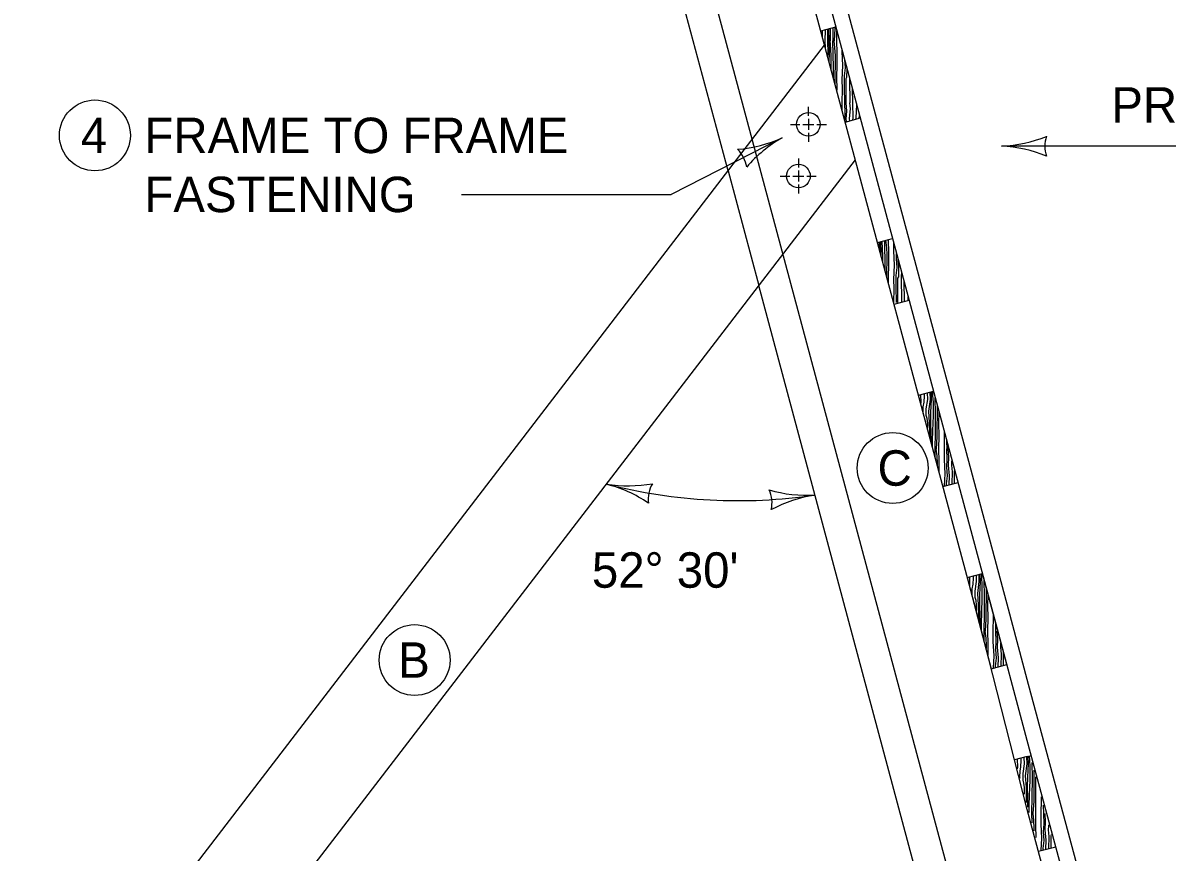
# Model space of a CAD drawing. Extents: x 49991 to 79985, y 47703 to 60542.
# Drawn here: x 50011.049 to 50012.986, y 49994.102 to 49995.507 of the extents above; entities that cross this region are included whole.
import ezdxf

# ---------------------------------------------------------------- set-up
doc = ezdxf.new("R2010")
doc.units = 0
for name, color, linetype in [('Level 1', 7, 'Continuous'), ('Level 2', 7, 'Continuous'), ('Level 3', 7, 'Continuous'), ('Level 33', 7, 'Continuous'), ('Level 4', 7, 'Continuous'), ('Level 5', 7, 'Continuous')]:
    doc.layers.add(name, color=color, linetype=linetype)

msp = doc.modelspace()

# ---------------------------------------------------------------- linework, layer by layer
at = {"layer": 'Level 1'}
for p, q in [((50012.7492, 49993.5717), (50012.0592, 49996.1469)), ((50012.6896, 49994.5138), (50012.2531, 49996.1429)), ((50012.7172, 49994.5138), (50012.2788, 49996.1497)), ((50012.2427, 49995.2562), (50012.0075, 49996.134)), ((50012.6693, 49994.4868), (50012.2343, 49996.1103)), ((50012.3996, 49995.4932), (50012.4253, 49995.5001)), ((50011.049, 49993.7005), (50012.4061, 49995.4691)), ((50012.441, 49995.3389), (50012.4667, 49995.3458)), ((50011.2503, 49993.7005), (50012.4582, 49995.2747)), ((50012.4956, 49995.135), (50012.5213, 49995.1419)), ((50012.655, 49993.7175), (50012.2948, 49995.0618)), ((50012.5237, 49995.0303), (50012.5493, 49995.0372)), ((50012.565, 49994.876), (50012.5907, 49994.8829)), ((50012.6063, 49994.7218), (50012.632, 49994.7286)), ((50012.6477, 49994.5675), (50012.6734, 49994.5744)), ((50012.9351, 49993.7005), (50012.7492, 49994.3944)), ((50012.9075, 49993.7005), (50012.7492, 49994.2915)), ((50012.7492, 49994.264), (50012.7561, 49994.2658)), ((50012.8544, 49993.782), (50012.7492, 49994.1747)), ((50012.7682, 49994.1037), (50012.7974, 49994.1115))]:
    msp.add_line(p, q, dxfattribs=at)
for points in [[(50012.4071, 49995.4763), (50012.4074, 49995.4953)], [(50012.4116, 49995.4763), (50012.4114, 49995.4963)], [(50012.4137, 49995.4763), (50012.4135, 49995.4969)], [(50012.4159, 49995.4763), (50012.416, 49995.4893), (50012.4162, 49995.4976)], [(50012.4204, 49995.4763), (50012.4208, 49995.4989)], [(50012.4227, 49995.4763), (50012.4239, 49995.4976), (50012.4239, 49995.4997)], [(50012.4025, 49995.4823), (50012.4025, 49995.4939)], [(50012.4074, 49995.464), (50012.407, 49995.4768)], [(50012.4114, 49995.4492), (50012.4123, 49995.4556), (50012.4115, 49995.4763)], [(50012.4136, 49995.4409), (50012.4144, 49995.4556), (50012.4136, 49995.4773)], [(50012.4173, 49995.4272), (50012.4173, 49995.4275), (50012.4173, 49995.4503), (50012.4166, 49995.4621), (50012.4157, 49995.4769)], [(50012.421, 49995.4133), (50012.4212, 49995.4308), (50012.4203, 49995.4767)], [(50012.424, 49995.4023), (50012.4243, 49995.4518), (50012.4237, 49995.4646), (50012.4224, 49995.4766)], [(50012.427, 49995.3909), (50012.4271, 49995.3944), (50012.4268, 49995.4145), (50012.4273, 49995.4351), (50012.4271, 49995.4556), (50012.4267, 49995.4768)], [(50012.4268, 49995.4763), (50012.427, 49995.4936)], [(50012.427, 49995.4936), (50012.427, 49995.4936)], [(50012.4359, 49995.3714), (50012.4365, 49995.3949), (50012.4359, 49995.4102), (50012.4371, 49995.4345), (50012.4359, 49995.4586), (50012.4359, 49995.4603)], [(50012.4136, 49995.4409), (50012.4136, 49995.4409)], [(50012.4405, 49995.3714), (50012.4399, 49995.3982), (50012.4396, 49995.4172), (50012.4413, 49995.4308), (50012.4402, 49995.4444)], [(50012.4173, 49995.4272), (50012.4173, 49995.4272)], [(50012.4427, 49995.3714), (50012.4424, 49995.408), (50012.4428, 49995.4125), (50012.444, 49995.4147), (50012.4444, 49995.4287)], [(50012.4444, 49995.4287), (50012.4444, 49995.4288)], [(50012.4494, 49995.3714), (50012.449, 49995.4114)], [(50012.4538, 49995.3714), (50012.4533, 49995.3953)], [(50012.4359, 49995.3577), (50012.4359, 49995.3717)], [(50012.4402, 49995.3418), (50012.4408, 49995.3542), (50012.4404, 49995.3715)], [(50012.4433, 49995.3395), (50012.4428, 49995.3442), (50012.4435, 49995.3575), (50012.4425, 49995.3715)], [(50012.4488, 49995.341), (50012.4485, 49995.3442), (50012.4487, 49995.3505), (50012.4501, 49995.3612), (50012.4491, 49995.3715)], [(50012.454, 49995.3424), (50012.4542, 49995.3452), (50012.4537, 49995.3717)], [(50012.459, 49995.3437), (50012.4594, 49995.346), (50012.4601, 49995.3565), (50012.4604, 49995.3687)], [(50012.4402, 49995.3418), (50012.4402, 49995.3418)], [(50012.4647, 49995.3453), (50012.4654, 49995.3501)], [(50012.4997, 49995.1197), (50012.4991, 49995.1359)], [(50012.5016, 49995.1124), (50012.5019, 49995.1175), (50012.5012, 49995.1365)], [(50012.5048, 49995.1005), (50012.5048, 49995.1122), (50012.5041, 49995.124), (50012.5033, 49995.1371)], [(50012.5086, 49995.0863), (50012.5087, 49995.0926), (50012.5078, 49995.1383)], [(50012.5115, 49995.0754), (50012.5118, 49995.1137), (50012.5112, 49995.1265), (50012.5098, 49995.1388)], [(50012.5145, 49995.0644), (50012.5143, 49995.0764), (50012.5148, 49995.0969), (50012.5146, 49995.1175), (50012.5142, 49995.14)], [(50012.5234, 49995.0333), (50012.524, 49995.0568), (50012.5234, 49995.0721), (50012.5246, 49995.0964), (50012.5234, 49995.1205), (50012.5234, 49995.1341)], [(50012.528, 49995.0333), (50012.5274, 49995.0601), (50012.5271, 49995.0791), (50012.5288, 49995.0926), (50012.5276, 49995.1072), (50012.528, 49995.1163)], [(50012.5302, 49995.0333), (50012.5299, 49995.0699), (50012.5303, 49995.0744), (50012.5315, 49995.0766), (50012.5319, 49995.0929), (50012.5308, 49995.1062)], [(50012.5369, 49995.0339), (50012.5365, 49995.0786), (50012.5366, 49995.0842)], [(50012.5413, 49995.0351), (50012.5406, 49995.0695)], [(50012.5478, 49995.0368), (50012.5478, 49995.0426)], [(50012.5478, 49995.0426), (50012.5478, 49995.0426)], [(50012.569, 49994.8607), (50012.5693, 49994.8637), (50012.569, 49994.8771)], [(50012.5732, 49994.8452), (50012.5729, 49994.8472), (50012.5731, 49994.8567), (50012.5745, 49994.8645), (50012.5752, 49994.875), (50012.5753, 49994.8788)], [(50012.5805, 49994.8181), (50012.5806, 49994.8291), (50012.5795, 49994.8368), (50012.5782, 49994.8419), (50012.5782, 49994.8529), (50012.5806, 49994.8692), (50012.5802, 49994.8801)], [(50012.5843, 49994.8039), (50012.5842, 49994.8101), (50012.5838, 49994.8299), (50012.5825, 49994.8492), (50012.5851, 49994.8692), (50012.5847, 49994.8813)], [(50012.5865, 49994.7957), (50012.5863, 49994.8101), (50012.5859, 49994.8299), (50012.5861, 49994.8469), (50012.5873, 49994.8692), (50012.5868, 49994.8819)], [(50012.5888, 49994.7871), (50012.5888, 49994.7981), (50012.5893, 49994.8166), (50012.5902, 49994.8412), (50012.5902, 49994.864), (50012.5895, 49994.8757), (50012.5891, 49994.8825)], [(50012.5933, 49994.785), (50012.5938, 49994.8133), (50012.594, 49994.8444), (50012.5935, 49994.8718)], [(50012.5935, 49994.8718), (50012.5935, 49994.8719)], [(50012.5955, 49994.785), (50012.5968, 49994.8063), (50012.5972, 49994.8584)], [(50012.5997, 49994.785), (50012.5999, 49994.8081), (50012.5997, 49994.8281), (50012.6001, 49994.8473)], [(50012.6088, 49994.785), (50012.6093, 49994.8086), (50012.6092, 49994.8136)], [(50012.613, 49994.7991), (50012.613, 49994.7992)], [(50012.6133, 49994.785), (50012.613, 49994.7991)], [(50012.5935, 49994.7695), (50012.5933, 49994.7855)], [(50012.5972, 49994.7558), (50012.5972, 49994.7606), (50012.5965, 49994.7734), (50012.5952, 49994.785)], [(50012.6002, 49994.7446), (50012.5999, 49994.7644), (50012.5997, 49994.7846)], [(50012.609, 49994.7225), (50012.61, 49994.7433), (50012.6088, 49994.7674), (50012.6088, 49994.7854)], [(50012.6125, 49994.7234), (50012.6125, 49994.726), (50012.6142, 49994.7395), (50012.613, 49994.7541), (50012.6137, 49994.7679), (50012.6132, 49994.7852)], [(50012.6169, 49994.7246), (50012.6173, 49994.7398), (50012.6157, 49994.7578), (50012.6164, 49994.7711), (50012.6154, 49994.7854)], [(50012.6156, 49994.785), (50012.6155, 49994.7897)], [(50012.6219, 49994.726), (50012.6225, 49994.7463), (50012.6214, 49994.7578), (50012.6216, 49994.7641), (50012.6219, 49994.7662)], [(50012.5972, 49994.7557), (50012.5972, 49994.7558)], [(50012.626, 49994.727), (50012.6261, 49994.7476), (50012.6263, 49994.7496)], [(50012.6519, 49994.5521), (50012.6522, 49994.5551), (50012.6519, 49994.5685)], [(50012.6561, 49994.5366), (50012.6558, 49994.5386), (50012.656, 49994.5481), (50012.6574, 49994.5559), (50012.6581, 49994.5664), (50012.6582, 49994.5702)], [(50012.6634, 49994.5095), (50012.6635, 49994.5205), (50012.6624, 49994.5282), (50012.6611, 49994.5333), (50012.6611, 49994.5443), (50012.6635, 49994.5606), (50012.6631, 49994.5715)], [(50012.6672, 49994.4953), (50012.6671, 49994.5015), (50012.6667, 49994.5213), (50012.6654, 49994.5406), (50012.668, 49994.5606), (50012.6676, 49994.5727)], [(50012.6694, 49994.4871), (50012.6692, 49994.5015), (50012.6688, 49994.5213), (50012.669, 49994.5383), (50012.6702, 49994.5606), (50012.6697, 49994.5733)], [(50012.6717, 49994.4785), (50012.6717, 49994.4895), (50012.6722, 49994.508), (50012.6731, 49994.5326), (50012.6731, 49994.5554), (50012.6724, 49994.5671), (50012.672, 49994.5739)], [(50012.6762, 49994.4764), (50012.6767, 49994.5047), (50012.6769, 49994.5358), (50012.6764, 49994.5632)], [(50012.6784, 49994.4764), (50012.6797, 49994.4977), (50012.6801, 49994.5498)], [(50012.6826, 49994.4764), (50012.6828, 49994.4995), (50012.6826, 49994.5195), (50012.683, 49994.5387)], [(50012.6832, 49994.5368), (50012.6832, 49994.5368)], [(50012.6917, 49994.4764), (50012.6922, 49994.5), (50012.6921, 49994.505)], [(50012.6962, 49994.4764), (50012.6959, 49994.4905)], [(50012.6764, 49994.4609), (50012.6762, 49994.4769)], [(50012.6801, 49994.4472), (50012.6801, 49994.452), (50012.6794, 49994.4648), (50012.6781, 49994.4764)], [(50012.6831, 49994.436), (50012.6828, 49994.4558), (50012.6826, 49994.4761)], [(50012.6919, 49994.4139), (50012.6929, 49994.4347), (50012.6917, 49994.4588), (50012.6917, 49994.4768)], [(50012.6954, 49994.4148), (50012.6954, 49994.4174), (50012.6971, 49994.4309), (50012.6959, 49994.4455), (50012.6966, 49994.4593), (50012.6962, 49994.4766)], [(50012.6998, 49994.416), (50012.7002, 49994.4312), (50012.6986, 49994.4492), (50012.6993, 49994.4625), (50012.6983, 49994.4768)], [(50012.7048, 49994.4174), (50012.7054, 49994.4377), (50012.7043, 49994.4492), (50012.7045, 49994.4555), (50012.7048, 49994.4576)], [(50012.7089, 49994.4184), (50012.709, 49994.439), (50012.7092, 49994.441)], [(50012.7328, 49994.2432), (50012.7331, 49994.2462), (50012.7328, 49994.2596)], [(50012.737, 49994.2277), (50012.7367, 49994.2297), (50012.7369, 49994.2392), (50012.7383, 49994.247), (50012.739, 49994.2575), (50012.7391, 49994.2613)], [(50012.7443, 49994.2006), (50012.7444, 49994.2116), (50012.7433, 49994.2193), (50012.742, 49994.2244), (50012.742, 49994.2354), (50012.7444, 49994.2517), (50012.744, 49994.2626)], [(50012.7481, 49994.1864), (50012.748, 49994.1926), (50012.7476, 49994.2124), (50012.7463, 49994.2317), (50012.7489, 49994.2517), (50012.7485, 49994.2638)], [(50012.7503, 49994.1782), (50012.7501, 49994.1926), (50012.7497, 49994.2124), (50012.7499, 49994.2294), (50012.7511, 49994.2517), (50012.7506, 49994.2644)], [(50012.7526, 49994.1696), (50012.7526, 49994.1806), (50012.7531, 49994.1991), (50012.754, 49994.2237), (50012.754, 49994.2465), (50012.7533, 49994.2582), (50012.7529, 49994.265)], [(50012.7571, 49994.1675), (50012.7576, 49994.1958), (50012.7578, 49994.2269), (50012.7573, 49994.2543)], [(50012.7593, 49994.1675), (50012.7606, 49994.1888), (50012.761, 49994.2409)], [(50012.7635, 49994.1675), (50012.7637, 49994.1906), (50012.7635, 49994.2106), (50012.7639, 49994.2298)], [(50012.7724, 49994.2042), (50012.7724, 49994.2042)], [(50012.7726, 49994.1675), (50012.7731, 49994.1911), (50012.773, 49994.1961)], [(50012.7771, 49994.1675), (50012.7768, 49994.1816)], [(50012.7573, 49994.152), (50012.7571, 49994.168)], [(50012.761, 49994.1383), (50012.761, 49994.1431), (50012.7603, 49994.1559), (50012.759, 49994.1675)], [(50012.764, 49994.1271), (50012.7637, 49994.1469), (50012.7635, 49994.1671)], [(50012.7728, 49994.105), (50012.7738, 49994.1258), (50012.7726, 49994.1499), (50012.7726, 49994.1679)], [(50012.7763, 49994.1059), (50012.7763, 49994.1085), (50012.778, 49994.122), (50012.7768, 49994.1366), (50012.7775, 49994.1504), (50012.7771, 49994.1677)], [(50012.7807, 49994.1071), (50012.7811, 49994.1223), (50012.7795, 49994.1403), (50012.7802, 49994.1536), (50012.7792, 49994.1679)], [(50012.7857, 49994.1085), (50012.7863, 49994.1288), (50012.7852, 49994.1403), (50012.7854, 49994.1466), (50012.7857, 49994.1487)], [(50012.7898, 49994.1095), (50012.7899, 49994.1301), (50012.7901, 49994.1321)], [(50012.7968, 49994.1114), (50012.7967, 49994.1126), (50012.7968, 49994.1138)]]:
    msp.add_lwpolyline(points, dxfattribs=at)
for centre in [(50012.3787, 49995.335), (50012.3618, 49995.2474)]:
    msp.add_circle(centre, 0.02, dxfattribs=at)
at = {"layer": 'Level 2'}
for centre in [(50011.1709, 49995.3163), (50012.5213, 49994.7529), (50011.7121, 49994.4276)]:
    msp.add_circle(centre, 0.06, dxfattribs=at)
at = {"layer": 'Level 3'}
for p, q in [((50012.3343, 49995.3123), (50012.1463, 49995.2163)), ((50013.5487, 49995.2979), (50012.7056, 49995.2979)), ((50011.7913, 49995.2163), (50012.1463, 49995.2163))]:
    msp.add_line(p, q, dxfattribs=at)
for centre, radius, start, end in [((50012.2414, 49995.5143), 0.2223, 274.5263, 294.7098), ((50012.4505, 49995.1103), 0.233, 119.8976, 139.1475), ((50012.6941, 49995.5306), 0.233, 272.8273, 292.0772), ((50012.8338, 49995.2979), 0.0548, 162.1388, 197.8612), ((50012.2201, 49995.254), 0.0548, 9.2091, 44.9315), ((50012.6964, 49995.0758), 0.2223, 67.456, 87.6395), ((50012.0739, 49994.9557), 0.233, 260.8756, 280.1255), ((50012.2596, 49995.5956), 0.898, 255.6408, 278.3383), ((50011.9819, 49994.5102), 0.2223, 55.5043, 75.6878), ((50012.1623, 49994.6991), 0.0548, 150.1871, 185.9095), ((50012.3758, 49994.929), 0.2223, 253.4462, 273.6297), ((50012.2623, 49994.6937), 0.0548, 348.129, 23.8514), ((50012.4256, 49994.4768), 0.233, 98.8175, 118.0674)]:
    msp.add_arc(centre, radius, start, end, dxfattribs=at)
at = {"layer": 'Level 33'}
for p, q in [((50012.6477, 49994.5675), (50012.6883, 49994.4128)), ((50012.7148, 49994.4199), (50012.6734, 49994.5744)), ((50012.7492, 49994.2915), (50012.6896, 49994.5138)), ((50012.7492, 49994.3944), (50012.7172, 49994.5138)), ((50012.7492, 49994.1747), (50012.6693, 49994.4868)), ((50012.6883, 49994.4128), (50012.7148, 49994.4199)), ((50012.7492, 49994.264), (50012.7277, 49994.2585))]:
    msp.add_line(p, q, dxfattribs=at)
at = {"layer": 'Level 4'}
msp.add_line((50012.2427, 49995.2562), (50012.2948, 49995.0618), dxfattribs=at)
at = {"layer": 'Level 5'}
for p, q in [((50012.3787, 49995.3495), (50012.3787, 49995.3645)), ((50012.3787, 49995.3443), (50012.3787, 49995.3258)), ((50012.3483, 49995.335), (50012.3642, 49995.335)), ((50012.3694, 49995.335), (50012.388, 49995.335)), ((50012.3932, 49995.335), (50012.4093, 49995.335)), ((50012.3787, 49995.3205), (50012.3787, 49995.3055)), ((50012.3618, 49995.2773), (50012.3618, 49995.2619)), ((50012.331, 49995.2474), (50012.3473, 49995.2474)), ((50012.3525, 49995.2474), (50012.371, 49995.2474)), ((50012.3618, 49995.2566), (50012.3618, 49995.2381)), ((50012.3763, 49995.2474), (50012.3918, 49995.2474)), ((50012.3618, 49995.2329), (50012.3618, 49995.2177))]:
    msp.add_line(p, q, dxfattribs=at)

# ---------------------------------------------------------------- texts
at = {"layer": 'Level 2'}
for s, p in [('PREVAILING', (50012.8914, 49995.3379)), ('4', (50011.147, 49995.2863)), ('FRAME TO FRAME', (50011.2547, 49995.2863)), ('FASTENING', (50011.2547, 49995.1863)), ('C', (50012.4957, 49994.7229)), ("52° 30'", (50012.0122, 49994.5501)), ('B', (50011.6843, 49994.3976))]:
    msp.add_text(s, height=0.06, dxfattribs=at).set_placement(p)

doc.saveas('drawing.dxf')
